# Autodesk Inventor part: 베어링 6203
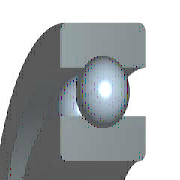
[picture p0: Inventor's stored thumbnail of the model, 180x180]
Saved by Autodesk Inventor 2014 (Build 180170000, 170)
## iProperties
IsCustomPart: 0
Created: 2016-05
Part Number: 베어링 6203
Material: 강철, 연강
Description: 깊은 그루브 볼 베어링
Document SubType Name: Modeling
Standard: KS B 2023
Designer: mduedu
Standards Organization: KS
Language: ko-KR
Size Designation: 6203 - 17 x 40 x 12
Categories: <MemberInstance><Categories><Category DisplayName="샤프트 부품" InternalName="7f7aeb1f-a693-4053-b835-cee3144e0d98" Mnemonic="SHFT"><Category DisplayName="베어링" Inter
Density: 1 g/cm^3
Appearance: 노란색
Author: mduedu
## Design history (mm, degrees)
sketch "스케치" dims "d0" = 5.98 (= -0.26 x WD + 0.26 x BD)
  geometry: L1 (3.01, 14.25)-(8.99, 14.25); L2 (6, 14.25)-(6, 11.26); L3 (6, 14.25)-(6, 17.24); L4 (3.778, 12.249)-(0, 12.249); L5 (0, 8.5)-(12, 8.5); L6 (3.778, 16.251)-(0, 16.251); L7 (0, 20)-(12, 20); L8 (12, 8.5)-(12, 12.249); L9 (8.222, 12.249)-(12, 12.249); L10 (8.222, 16.251)-(12, 16.251); L11 (12, 20)-(12, 16.251); L12 (-1.4, 0)-(8.4, 0) reference; L13 (0, -0.3)-(0, 5.3) reference
  constraints: 22 end point, 4 point on line, 2 collinear, 2 perpendicular, 2 symmetric about line, 1 midpoint, 1 parallel, 14 other
  dimensions: "d9" = 17 diameter of L5 L12 (= WD); "d11" = 40 diameter of L7 L12 (= BD); "d12" = 12 distance between parallel lines of L8 L13 (= KB); "d13" = 24.498 diameter of L9 L12 (= 0.326 x BD + 0.674 x WD)
revolve "본체" stored, may be unused: angle "d6" = 90 deg
revolve "볼" stored, may be unused: angle "d7" = 90 deg
pattern_circular "IDS_ARRAYBALL[SIMPL:T]" dims angle "d3" = 360 deg
body "Solid1"
fillet "모깎기1" dims "d1" = 0.6 (= KRS)
other parameters: "WD" = 17 [user parameter; used in 5 equation terms], "BD" = 40 [user parameter; used in 5 equation terms], "KB" = 12 [user parameter; used in 1 equation term], "KRS" = 0.6 [user parameter; used in 1 equation term], "d4" = 0, "d5" = 0, "d8" = 0, "d14" = 0, "d15" = 0, "BBA" = 0 [user parameter], "BC0" = 4750000 [user parameter], "BC" = 9560000 [user parameter], "WR" = 8.5 (= 0.5 x WD) [user parameter]
